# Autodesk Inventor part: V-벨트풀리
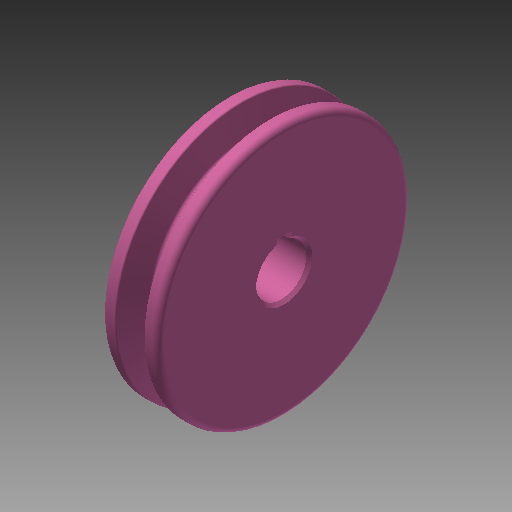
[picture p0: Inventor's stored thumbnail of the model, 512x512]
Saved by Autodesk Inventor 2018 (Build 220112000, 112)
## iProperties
Created: 2018-11
Part Number: V-벨트풀리
Material: 알루미늄 6061
Document SubType Name: Modeling
Designer: mduedu
Density: 1 g/cm^3
Appearance: 분홍색
Author: mduedu
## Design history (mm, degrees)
sketch "스케치1"
  geometry: L1 (-9.5, 0)-(9.5, 0); L2 (9.5, 0)-(9.5, 42.7); L3 (9.5, 42.7)-(-9.5, 42.7); L4 (-9.5, 42.7)-(-9.5, 0); L5 (-4.877, 42.7)-(-1.953, 33.7); L6 (-1.953, 33.7)-(1.953, 33.7); L7 (1.953, 33.7)-(4.877, 42.7); L8 (0, 0)-(0, 42.7); L9 (-9.5, 40)-(9.5, 40); 3 further points
  constraints: 18 end point, 8 point on line, 3 perpendicular, 2 midpoint, 2 parallel, 1 coincident, 1 horizontal, 1 other
  dimensions: "d0" = 85.4 diameter of L3 L1; "d2" = 19 distance of L2.end L3.end; "d3" = 80 diameter of L9 L1; "d4" = 36 deg angle of L7 L5; "d5" = 6.3 distance between parallel lines of L6 L9; "d6" = 8 distance of point (4, 40) point (-4, 40)
revolve "회전1" sketch "스케치1" stored, may be unused: angle "d7" = 90 deg
sketch "스케치2"
  geometry: L1 (-2.5, 8.124)-(2.5, 8.124); L2 (2.5, 8.124)-(2.5, 10.8); L3 (2.5, 10.8)-(-2.5, 10.8); L4 (-2.5, 10.8)-(-2.5, 8.124); A1 r 8.5 centre (0, 0) between (-2.5, 8.124) and (2.5, 8.124); 1 further point
  constraints: 8 end point, 2 parallel, 2 point on circle, 1 centre point, 1 coincident, 1 horizontal, 1 perpendicular
  dimensions: "d8" = 17 diameter of A1; "d10" = 19.3 dimension on A1 L3; "d11" = 5 distance of L2.end L3.end
extrude "돌출1" cut sketch "스케치2" extent not by distance; stored distance "d12" = 10; taper "d13" = 0 deg
chamfer "모따기1" distance "d14" = 1; stored, may be unused: second distance "d15" = 2, angle "d16" = 45 deg
fillet "모깎기1" dims "d17" = 1, "d18" = 0.5, "d19" = 2
sketch "스케치3"
  geometry: C1 r 17.5 at (0, 0); C2 r 28.5 at (0, 0); 1 further point
  constraints: 2 centre point, 2 coincident
  dimensions: "d20" = 35 diameter of C1; "d23" = 57 diameter of C2
extrude "돌출2" cut sketch "스케치3" distance "d24" = 9.5; taper "d25" = 0 deg
fillet "모깎기2" dims "d26" = 3
node "솔리드1"
